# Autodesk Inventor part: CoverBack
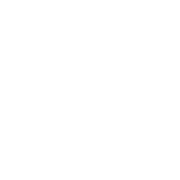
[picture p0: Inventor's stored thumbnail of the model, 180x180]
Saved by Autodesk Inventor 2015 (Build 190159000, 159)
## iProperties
Created: 2016-02
Part Number: CoverBack
Material: Wood (Birch)
Document SubType Name: Modeling
Designer: Hafliði
Density: 0.55 g/cm^3
Appearance: Birch - Natural Polished
Mass: 78.925 g
Surface Area: 342 cm^2
Volume: 143.5 cm^3
Author: Hafliði
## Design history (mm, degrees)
sketch "Sketch1"
  geometry: L1 (-102.5, 35)-(102.5, 35); L2 (102.5, 35)-(102.5, -35); L3 (102.5, -35)-(-102.5, -35); L4 (-102.5, -35)-(-102.5, 35); L5 (-102.5, 35)-(102.5, -35); L6 (102.5, 35)-(-102.5, -35); 1 further point
  constraints: 12 end point, 2 midpoint, 2 parallel, 1 horizontal, 1 perpendicular
  dimensions: "d0" = 205 distance of L2.end L3.end; "d1" = 70 distance of L1.end L2.end
extrude "Extrusion1" new body sketch "Sketch1" distance "d2" = 10; taper "d3" = 0 deg
body "Solid1"
